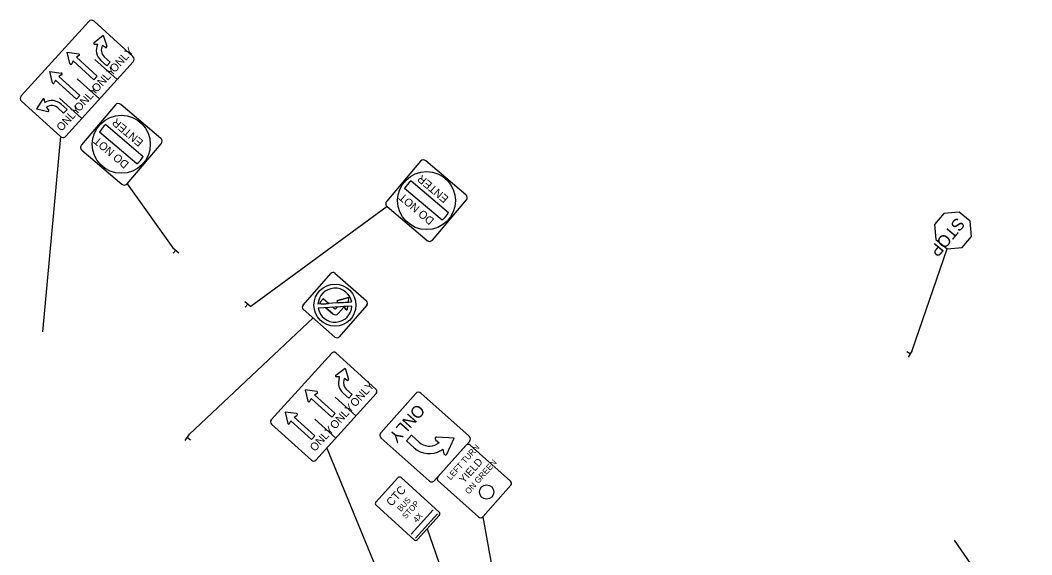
# Model space of a CAD drawing. Extents: x 1472333 to 1475205, y 385587 to 386650.
# Drawn here: x 1472913.2 to 1473334.4, y 385966.6 to 386189.3 of the extents above; entities that cross this region are included whole.
import ezdxf

# ---------------------------------------------------------------- set-up
doc = ezdxf.new("R2010")
doc.units = 0
doc.layers.add('RW_X_CL', color=7, linetype='Continuous')
doc.layers.add('RW_X_CL_500_Cardinal_Points', color=7, linetype='Continuous')

msp = doc.modelspace()

# ---------------------------------------------------------------- linework, layer by layer
at = {"layer": 'RW_X_CL'}
for p, q in [((1472943.99, 386179.96), (1472947.73, 386183.02)), ((1472947.73, 386183.02), (1472949.25, 386178.43)), ((1472945.37, 386179.24), (1472944.26, 386179.22)), ((1472948.62, 386177.95), (1472947.46, 386178.73)), ((1472932.74, 386175.95), (1472937.54, 386175.3)), ((1472933.86, 386171.24), (1472932.74, 386175.95)), ((1472937.69, 386174.53), (1472936.58, 386173.87)), ((1472936.58, 386173.87), (1472945.25, 386166.01)), ((1472953.47, 386164.54), (1472944.21, 386172.93)), ((1472949.17, 386170.34), (1472946.57, 386172.69)), ((1472946.57, 386172.69), (1472946.77, 386172.5)), ((1472948.17, 386174.05), (1472950.57, 386171.88)), ((1472935.18, 386172.33), (1472934.64, 386171.16)), ((1472943.85, 386164.47), (1472935.18, 386172.33)), ((1472950.57, 386171.88), (1472949.17, 386170.34)), ((1472925.47, 386167.92), (1472930.26, 386167.27)), ((1472926.58, 386163.22), (1472925.47, 386167.92)), ((1472927.9, 386164.31), (1472927.36, 386163.14)), ((1472936.57, 386156.45), (1472927.9, 386164.31)), ((1472930.41, 386166.5), (1472929.3, 386165.85)), ((1472929.3, 386165.85), (1472937.97, 386157.99)), ((1472946.16, 386156.47), (1472936.9, 386164.87)), ((1472945.25, 386166.01), (1472943.85, 386164.47)), ((1472922.57, 386156.34), (1472919.89, 386152.31)), ((1472923.42, 386155.03), (1472923.33, 386156.14)), ((1472938.84, 386148.41), (1472929.58, 386156.8)), ((1472937.97, 386157.99), (1472936.57, 386156.45)), ((1472919.89, 386152.31), (1472924.6, 386151.25)), ((1472925.02, 386151.92), (1472924.13, 386153.01)), ((1472928.86, 386152.75), (1472931.25, 386150.58)), ((1472932.65, 386152.12), (1472930.06, 386154.47)), ((1472930.06, 386154.47), (1472930.26, 386154.3)), ((1472931.25, 386150.58), (1472932.65, 386152.12)), ((1472948.83, 386145.78), (1472964.39, 386132.58)), ((1472929.89, 386140.85), (1472922.44, 386059.53)), ((1472961.7, 386129.4), (1472946.13, 386142.61)), ((1473075.94, 386122.32), (1473091.51, 386109.12)), ((1472957.72, 386121.17), (1472976.72, 386094.46)), ((1473088.81, 386105.94), (1473073.24, 386119.14)), ((1473065.95, 386111.67), (1473009.15, 386070.01)), ((1473304.17, 386109.39), (1473297.83, 386108.83)), ((1473308.76, 386105.53), (1473304.17, 386109.39)), ((1473297.83, 386108.83), (1473293.97, 386104.24)), ((1473309.32, 386099.19), (1473308.76, 386105.53)), ((1473293.97, 386104.24), (1473294.53, 386097.9)), ((1473294.53, 386097.9), (1473299.12, 386094.04)), ((1473305.46, 386094.6), (1473309.32, 386099.19)), ((1472976.72, 386094.46), (1472979.18, 386092.4)), ((1472977.95, 386093.43), (1472976.92, 386092.2)), ((1473284.59, 386051.7), (1473299.12, 386094.04)), ((1473299.12, 386094.04), (1473305.46, 386094.6)), ((1473006.7, 386072.06), (1473009.15, 386070.01)), ((1473037.96, 386071.65), (1473039.33, 386073.22)), ((1473039.33, 386073.22), (1473037.96, 386071.65)), ((1473038.64, 386071.05), (1473037.96, 386071.65)), ((1473037.96, 386071.65), (1473038.64, 386071.05)), ((1473041.58, 386071.24), (1473039.33, 386073.22)), ((1473041.58, 386071.24), (1473039.33, 386073.22)), ((1473045.32, 386071.79), (1473045.91, 386071.53)), ((1473045.32, 386071.79), (1473045.91, 386071.53)), ((1473045.39, 386072.58), (1473050.07, 386073.76)), ((1473050.07, 386073.76), (1473045.39, 386072.58)), ((1473045.91, 386071.52), (1473049.84, 386071.78)), ((1473049.84, 386071.78), (1473050.07, 386073.76)), ((1473049.84, 386071.78), (1473050.07, 386073.76)), ((1473007.92, 386071.03), (1473006.9, 386069.81)), ((1473051.3, 386070.2), (1473037.26, 386069.3)), ((1473038.64, 386071.05), (1473040.38, 386071.17)), ((1473040.38, 386071.17), (1473041.58, 386071.24)), ((1473043.28, 386066.98), (1473040.41, 386069.5)), ((1473040.49, 386069.5), (1473040.41, 386069.5)), ((1473040.41, 386069.5), (1473043.28, 386066.98)), ((1473043.35, 386069.69), (1473040.49, 386069.5)), ((1473043.89, 386069.21), (1473043.35, 386069.69)), ((1473043.89, 386069.21), (1473043.35, 386069.69)), ((1473044.74, 386069.27), (1473045.21, 386069.81)), ((1473045.21, 386069.81), (1473044.74, 386069.27)), ((1473049.64, 386070.1), (1473045.21, 386069.81)), ((1473045.63, 386067.13), (1473048.06, 386069.9)), ((1473045.63, 386067.13), (1473048.06, 386069.9)), ((1473048.73, 386068.8), (1473048.06, 386069.9)), ((1473048.06, 386069.9), (1473048.73, 386068.8)), ((1473049.5, 386068.96), (1473049.64, 386070.1)), ((1473049.5, 386068.96), (1473049.64, 386070.1)), ((1473035.17, 386065.23), (1472983.69, 386016.77)), ((1473283.76, 386050.33), (1473282.39, 386051.16)), ((1473284.59, 386051.7), (1473282.92, 386048.97)), ((1473044.65, 386041.46), (1473048.5, 386044.38)), ((1473048.5, 386044.38), (1473049.86, 386039.74)), ((1473046.19, 386040.69), (1473044.9, 386040.71)), ((1473045.99, 386040.09), (1473046.19, 386040.69)), ((1473048.17, 386040.04), (1473047.97, 386039.43)), ((1473049.21, 386039.29), (1473048.17, 386040.04)), ((1473031.84, 386035.31), (1473032.95, 386030.61)), ((1473036.63, 386034.66), (1473031.84, 386035.31)), ((1473035.67, 386033.24), (1473036.78, 386033.89)), ((1473050, 386031.77), (1473047.61, 386033.94)), ((1473049.01, 386035.49), (1473051.4, 386033.32)), ((1473033.73, 386030.53), (1473034.27, 386031.7)), ((1473034.27, 386031.7), (1473042.87, 386023.9)), ((1473044.27, 386025.45), (1473035.67, 386033.24)), ((1473044.3, 386032.31), (1473052.94, 386024.47)), ((1473051.4, 386033.32), (1473050, 386031.77)), ((1473023.44, 386026.05), (1473024.55, 386021.34)), ((1473028.23, 386025.4), (1473023.44, 386026.05)), ((1473042.87, 386023.9), (1473044.27, 386025.45)), ((1473025.33, 386021.27), (1473025.88, 386022.44)), ((1473025.88, 386022.44), (1473034.47, 386014.64)), ((1473027.28, 386023.98), (1473028.39, 386024.63)), ((1473035.87, 386016.19), (1473027.28, 386023.98)), ((1473035.9, 386023.05), (1473044.55, 386015.21)), ((1472981.82, 386014.17), (1472983.69, 386016.77)), ((1472982.76, 386015.47), (1472984.06, 386014.54)), ((1473034.47, 386014.64), (1473035.87, 386016.19)), ((1473040.78, 386011.06), (1473080.47, 385914.7)), ((1473085.07, 385985.26), (1473075.94, 385975.18)), ((1473086.93, 385983.58), (1473077.79, 385973.5)), ((1473082.62, 385977.39), (1473115.53, 385882.62)), ((1473302.04, 385972.65), (1473334.41, 385926.07))]:
    msp.add_line(p, q, dxfattribs=at)
for points in [[(1472941.7, 386188.78), (1472913.57, 386157.75)], [(1472960.11, 386174.19), (1472943.91, 386188.88)], [(1472932.09, 386140.96), (1472960.22, 386171.98)], [(1472913.68, 386155.55), (1472929.89, 386140.85)], [(1472952.8, 386154.02), (1472938.66, 386137.34)], [(1472971.69, 386140.05), (1472955.01, 386154.2)], [(1472938.84, 386135.13), (1472955.52, 386120.99)], [(1472957.72, 386121.17), (1472971.87, 386137.85)], [(1473079.92, 386130.56), (1473065.77, 386113.87)], [(1473098.8, 386116.59), (1473082.12, 386130.74)], [(1473084.84, 386097.7), (1473098.98, 386114.39)], [(1473065.95, 386111.67), (1473082.63, 386097.52)], [(1473030.94, 386070.61), (1473042.49, 386083.75)], [(1473044.25, 386083.87), (1473057.4, 386072.32)], [(1473051.19, 386071.87), (1473043.24, 386071.35), (1473040.38, 386071.17)], [(1473045.91, 386071.53), (1473045.91, 386071.52)], [(1473044.2, 386057.29), (1473031.05, 386068.84)], [(1473040.38, 386071.17), (1473037.15, 386070.96)], [(1473057.51, 386070.55), (1473045.96, 386057.41)], [(1473042.89, 386050.6), (1473017.7, 386022.82)], [(1473061.32, 386035.57), (1473044.65, 386050.69)], [(1473036.22, 386006.03), (1473061.41, 386033.81)], [(1473017.78, 386021.05), (1473034.45, 386005.94)], [(1473061.28, 385988.57), (1473070.42, 385998.65)], [(1473071.79, 385998.72), (1473087.63, 385984.36)], [(1473077.18, 385972.84), (1473061.35, 385987.2)], [(1473087.69, 385982.98), (1473078.55, 385972.91)]]:
    msp.add_lwpolyline(points, dxfattribs=at)
for centre, radius in [((1472955.26, 386137.59), 12.08), ((1473082.38, 386114.13), 12.08), ((1473044.23, 386070.58), 8.75)]:
    msp.add_circle(centre, radius, dxfattribs=at)
for centre, radius, start, end in [((1472942.86, 386187.73), 1.56, 47.8, 137.8), ((1472944.25, 386179.64), 0.417, 129.2602, 271.1383), ((1472950.69, 386176.83), 5.84, 155.568, 227.8), ((1472950.69, 386176.83), 3.75, 149.5767, 227.8), ((1472948.85, 386178.3), 0.417, 236.4147, 18.2928), ((1472937.48, 386174.89), 0.417, 300.4382, 82.3163), ((1472959.06, 386173.03), 1.56, 317.8, 47.8), ((1472934.26, 386171.34), 0.417, 193.2837, 335.1618), ((1472930.2, 386166.86), 0.417, 300.4382, 82.3163), ((1472926.98, 386163.31), 0.417, 193.2837, 335.1618), ((1472914.73, 386156.7), 1.56, 137.8, 227.8), ((1472922.91, 386156.11), 0.417, 4.4617, 146.3398), ((1472926.34, 386149.97), 5.84, 47.8, 120.032), ((1472926.34, 386149.97), 3.75, 47.8, 126.0233), ((1472924.7, 386151.66), 0.417, 257.3072, 39.1853), ((1472954, 386153.01), 1.56, 49.7, 139.7), ((1472955.26, 386137.59), 10.42, 128.163, 151.237), ((1472930.94, 386142.01), 1.56, 227.8, 317.8), ((1472970.68, 386138.86), 1.56, 319.7, 49.7), ((1472939.85, 386136.33), 1.56, 139.7, 229.7), ((1472955.26, 386137.59), 10.42, 308.163, 331.237), ((1473081.11, 386129.55), 1.56, 49.7, 139.7), ((1473082.38, 386114.13), 10.42, 128.163, 151.237), ((1472956.53, 386122.18), 1.56, 229.7, 319.7), ((1473066.96, 386112.86), 1.56, 139.7, 229.7), ((1473097.79, 386115.4), 1.56, 319.7, 49.7), ((1473082.38, 386114.13), 10.42, 308.163, 331.237), ((1473083.64, 386098.72), 1.56, 229.7, 319.7), ((1473043.43, 386082.93), 1.25, 48.7, 138.7), ((1473044.23, 386070.58), 7.08, 10.4563, 176.9437), ((1473044.23, 386070.58), 7.08, 10.4563, 176.9437), ((1473045.49, 386072.18), 0.417, 104.1837, 246.0618), ((1473045.49, 386072.18), 0.417, 104.1837, 246.0618), ((1473056.58, 386071.38), 1.25, 318.7, 48.7), ((1473031.88, 386069.78), 1.25, 138.7, 228.7), ((1473044.23, 386070.58), 7.08, 190.4563, 356.9437), ((1473044.29, 386069.66), 0.6, 228.7, 318.7), ((1473044.29, 386069.66), 0.6, 228.7, 318.7), ((1473049.09, 386069.01), 0.417, 211.3382, 353.2163), ((1473049.09, 386069.01), 0.417, 211.3382, 353.2163), ((1473044.38, 386068.23), 1.67, 228.7, 318.7), ((1473044.38, 386068.23), 1.67, 228.7, 318.7), ((1473045.03, 386058.23), 1.25, 228.7, 318.7), ((1473043.81, 386049.76), 1.25, 47.8, 137.8), ((1473044.91, 386041.13), 0.417, 127.2403, 269.1184), ((1473051.53, 386038.26), 5.83, 161.7101, 227.8), ((1473051.53, 386038.26), 3.75, 161.6986, 227.8), ((1473049.46, 386039.63), 0.417, 234.3948, 16.2729), ((1473036.57, 386034.25), 0.417, 300.4382, 82.3163), ((1473060.48, 386034.65), 1.25, 317.8, 47.8), ((1473033.35, 386030.7), 0.417, 193.2837, 335.1618), ((1473028.18, 386024.99), 0.417, 300.4382, 82.3163), ((1473018.62, 386021.98), 1.25, 137.8, 227.8), ((1473024.96, 386021.44), 0.417, 193.2837, 335.1618), ((1473035.29, 386006.87), 1.25, 227.8, 317.8), ((1473071.14, 385998), 0.972, 47.7891, 137.7891), ((1473062, 385987.92), 0.972, 137.7891, 227.7891), ((1473086.97, 385983.64), 0.972, 317.7891, 47.7891), ((1473077.83, 385973.56), 0.972, 227.7891, 317.7891)]:
    msp.add_arc(centre, radius, start, end, dxfattribs=at)
at = {"layer": 'RW_X_CL_500_Cardinal_Points'}
for p, q in [((1473076.04, 386016.39), (1473073.96, 386014.06)), ((1473073.96, 386014.06), (1473077.22, 386011.15)), ((1473079.3, 386013.48), (1473076.04, 386016.39)), ((1473086.17, 386014.54), (1473087.6, 386013.25)), ((1473093.89, 386015.13), (1473086.63, 386015.63)), ((1473087.6, 386013.25), (1473086.75, 386012.74)), ((1473090.8, 386008.54), (1473093.89, 386015.13)), ((1473088.33, 386010.05), (1473089.18, 386010.55)), ((1473089.18, 386010.55), (1473089.62, 386008.67)), ((1473105.79, 385982.46), (1473134.57, 385821.78))]:
    msp.add_line(p, q, dxfattribs=at)
for points in [[(1473077.85, 386033.76), (1473063.29, 386017.43)], [(1473100.11, 386016), (1473080.05, 386033.89)], [(1473063.41, 386015.23), (1473083.47, 385997.34)], [(1473085.68, 385997.47), (1473100.24, 386013.79)], [(1473087.13, 385999.1), (1473098.78, 386012.16)], [(1473100.54, 386012.26), (1473117.34, 385997.29)], [(1473104.03, 385982.36), (1473087.23, 385997.34)], [(1473117.44, 385995.52), (1473105.79, 385982.46)]]:
    msp.add_lwpolyline(points, dxfattribs=at)
msp.add_circle((1473107.4, 385992.75), 3, dxfattribs=at)
for centre, radius, start, end in [((1473079.01, 386032.72), 1.56, 48.2737, 138.2737), ((1473064.45, 386016.39), 1.56, 138.2737, 228.2737), ((1473083.53, 386018.22), 6.35, 228.2737, 300.4124), ((1473086.59, 386015.01), 0.625, 86.028, 227.7998), ((1473099.71, 386011.33), 1.25, 48.2737, 138.2737), ((1473099.07, 386014.83), 1.56, 318.2737, 48.2737), ((1473083.53, 386018.22), 9.48, 228.2737, 300.4163), ((1473090.23, 386008.81), 0.625, 193.0673, 334.8391), ((1473084.51, 385998.51), 1.56, 228.2737, 318.2737), ((1473088.07, 385998.27), 1.25, 138.2737, 228.2737), ((1473116.51, 385996.35), 1.25, 318.2737, 48.2737), ((1473104.86, 385983.29), 1.25, 228.2737, 318.2737)]:
    msp.add_arc(centre, radius, start, end, dxfattribs=at)

# ---------------------------------------------------------------- texts
at = {"layer": 'RW_X_CL'}
for s, height, rotation, p in [('ONLY', 3.333, 47.8, (1472952.53, 386167.22)), ('ONLY', 3.333, 47.8, (1472945.05, 386158.97)), ('ONLY', 3.333, 47.8, (1472937.77, 386150.94)), ('ONLY', 3.333, 47.8, (1472930.36, 386142.77)), ('ENTER', 3.333, 139.7, (1472964.71, 386138.87)), ('DO NOT', 3.333, 139.7, (1472958.72, 386129.74)), ('ENTER', 3.333, 139.7, (1473091.83, 386115.4)), ('DO NOT', 3.333, 139.7, (1473085.83, 386106.28)), ('STOP', 5, 230, (1473303.18, 386107.44)), ('ONLY', 3.333, 47.8, (1473052.66, 386027.88)), ('ONLY', 3.333, 47.8, (1473044.26, 386018.62)), ('ONLY', 3.333, 47.8, (1473035.87, 386009.36)), ('CTC', 3.4, 47.7891, (1473067.75, 385986.52)), ('BUS', 2.38, 47.7891, (1473071.63, 385984.36)), ('STOP', 2.38, 47.7891, (1473073.73, 385981.37)), ('4X', 2.38, 47.7891, (1473078.3, 385979.84))]:
    msp.add_text(s, height=height, rotation=rotation, dxfattribs=at).set_placement(p)
at = {"layer": 'RW_X_CL_500_Cardinal_Points'}
for s, height, rotation, p in [('ONLY', 5, 228.2737, (1473078.45, 386029.74)), ('LEFT TURN', 2.503, 48.2737, (1473092.37, 385997.49)), ('YIELD', 3.128, 48.2737, (1473097.98, 385996.11)), ('ON GREEN', 2.503, 48.2737, (1473099.97, 385991.6))]:
    msp.add_text(s, height=height, rotation=rotation, dxfattribs=at).set_placement(p)

doc.saveas('drawing.dxf')
